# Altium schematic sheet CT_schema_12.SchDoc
size 382 x 278 mm
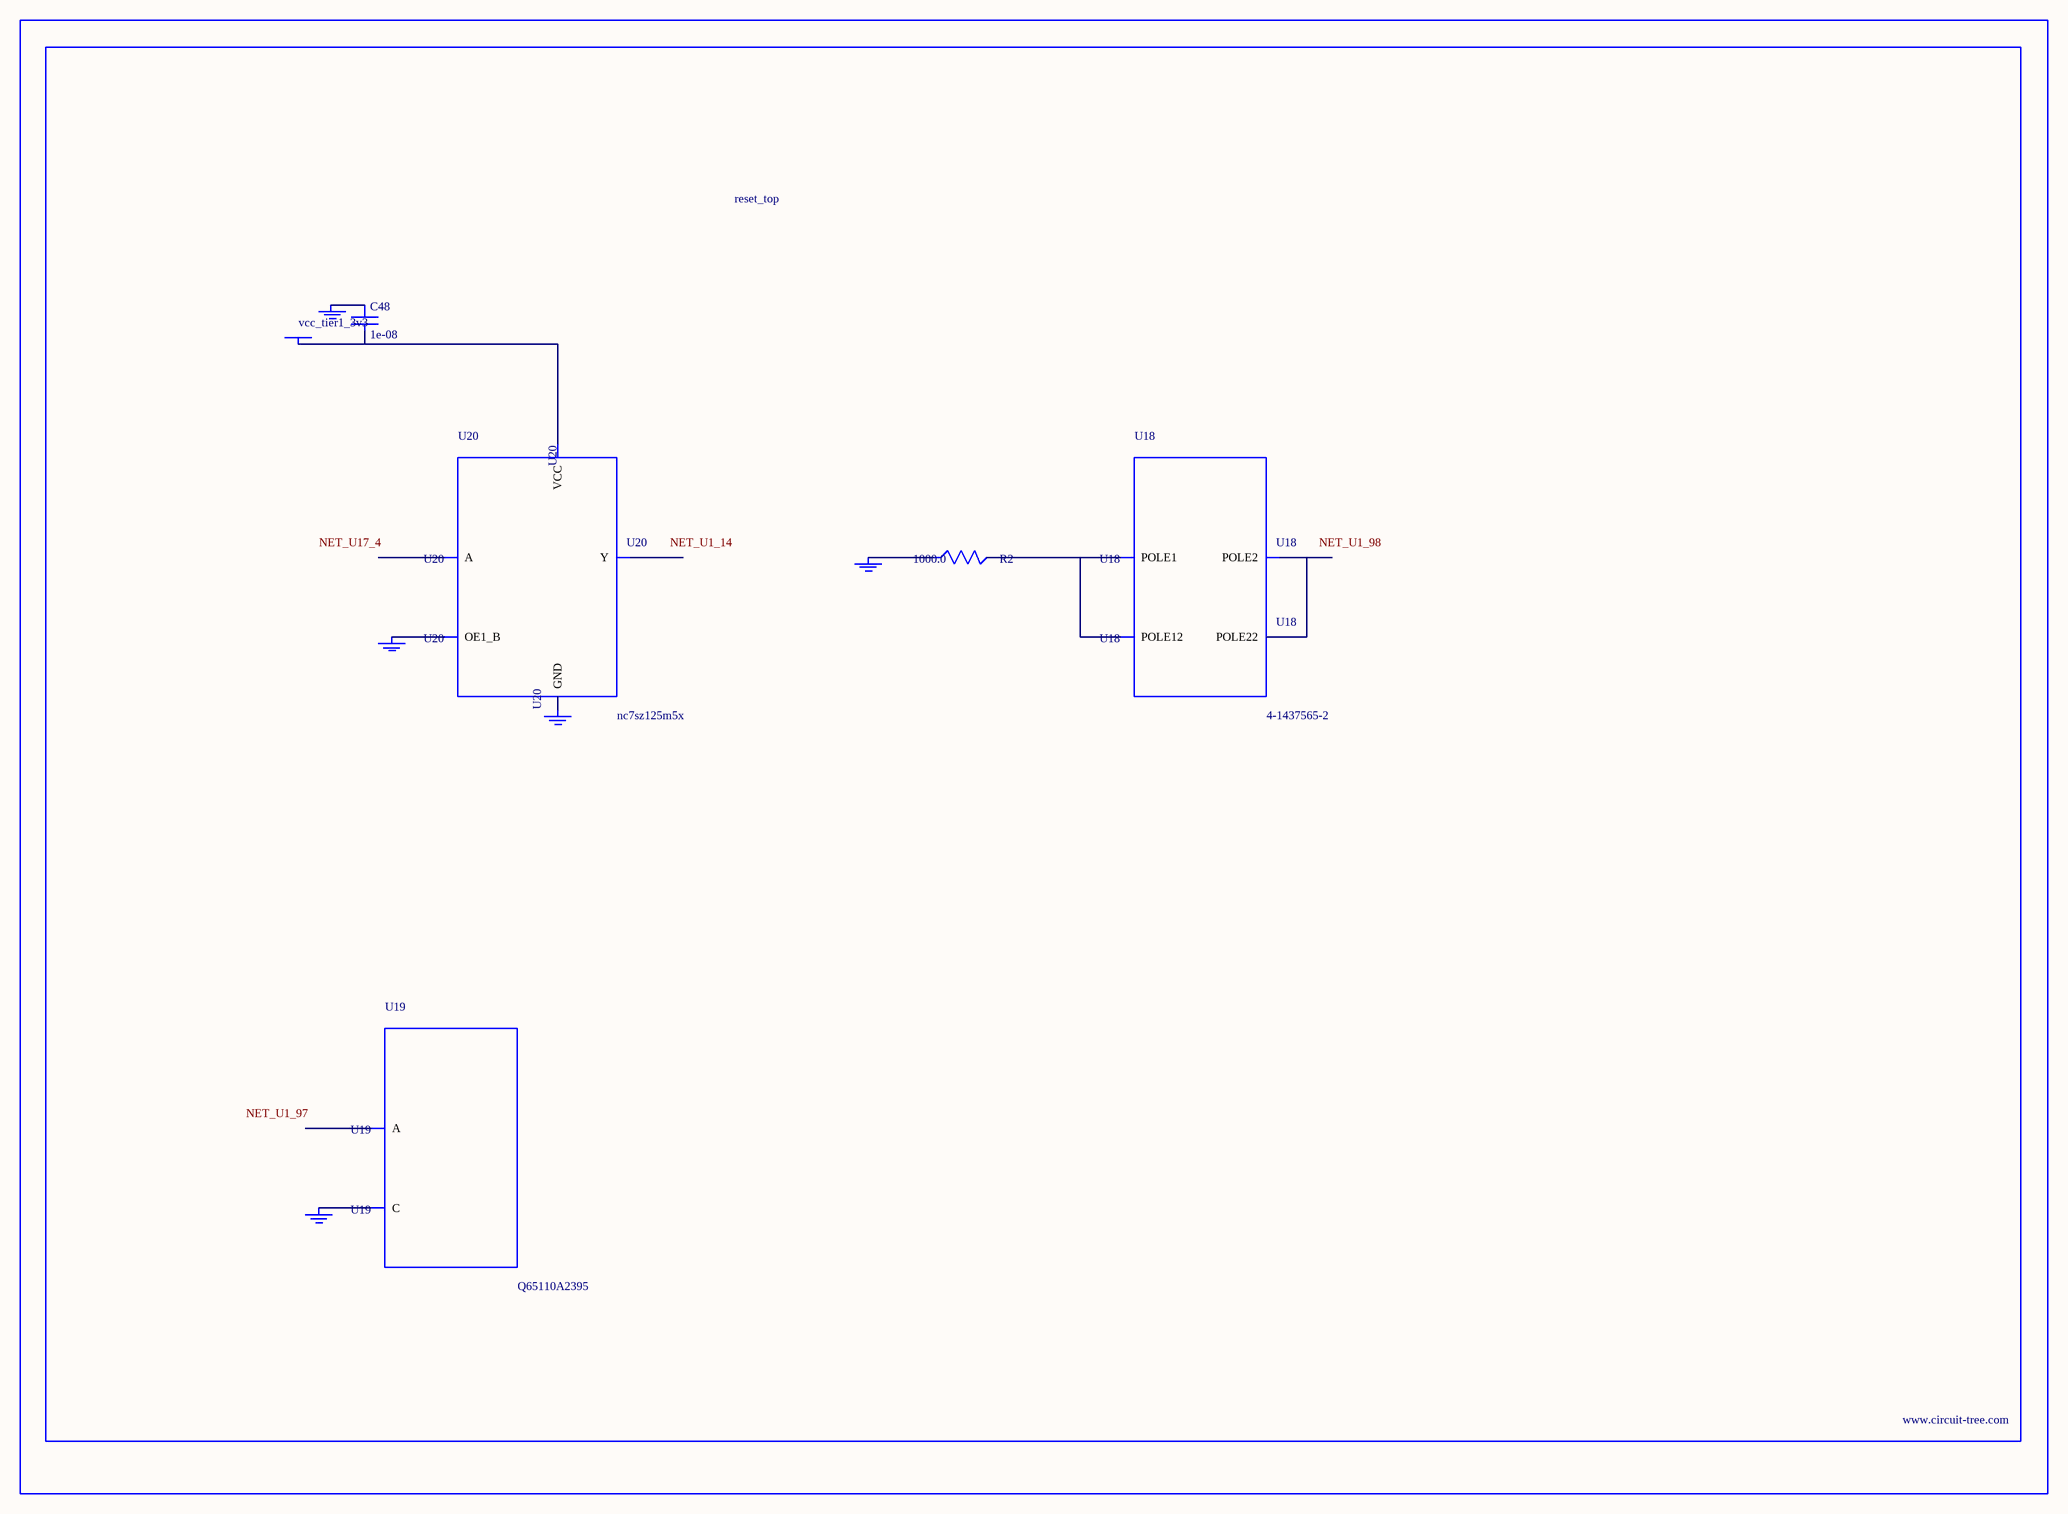
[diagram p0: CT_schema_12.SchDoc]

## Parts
BORDER11  (no value)
C48  1e-08  [C0402]
GND_INSTANCE_11_0  (no value)
GND_INSTANCE_11_1  (no value)
GND_INSTANCE_11_2  (no value)
GND_INSTANCE_11_3  (no value)
GND_INSTANCE_11_4  (no value)
POWER_INSTANCE_11_0  vcc_tier1_3v3
R2  1000.0  [R0603]
U18  4-1437565-2  [SW_4-1437565-2]
U19  Q65110A2395  [LGM67K-G1J2-24-Z]
U20  nc7sz125m5x  [NC7SZ125M5X]

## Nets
NetC48_1: C48.1 GND_INSTANCE_11_2.0(GND)
NetC48_2: C48.2 POWER_INSTANCE_11_0.0(PWR) U20.5(VCC)
NetGND_INSTANCE_11_0_0: GND_INSTANCE_11_0.0(GND) R2.1
NetGND_INSTANCE_11_1_0: GND_INSTANCE_11_1.0(GND) U19.C
NetGND_INSTANCE_11_3_0: GND_INSTANCE_11_3.0(GND) U20.1(OE1_B)
NetGND_INSTANCE_11_4_0: GND_INSTANCE_11_4.0(GND) U20.3(GND)
NetR2_2: R2.2 U18.1(POLE1) U18.2(POLE12)
NetU18_3: U18.3(POLE2) U18.4(POLE22)

Not connected (* = marked no-connect by the designer): U19 A; U20 2(A) 4(Y)

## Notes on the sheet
- Labels drawn without touching a wire or pin: NET_U1_14, NET_U1_97, NET_U1_98, NET_U17_4

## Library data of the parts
BORDER11 = BORDER_PAGE11
C48 = C0402C103K3RAC
GND_INSTANCE_11_0-GND_INSTANCE_11_4 = GND
POWER_INSTANCE_11_0 = PWR
R2 = RC0603JR-071KL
